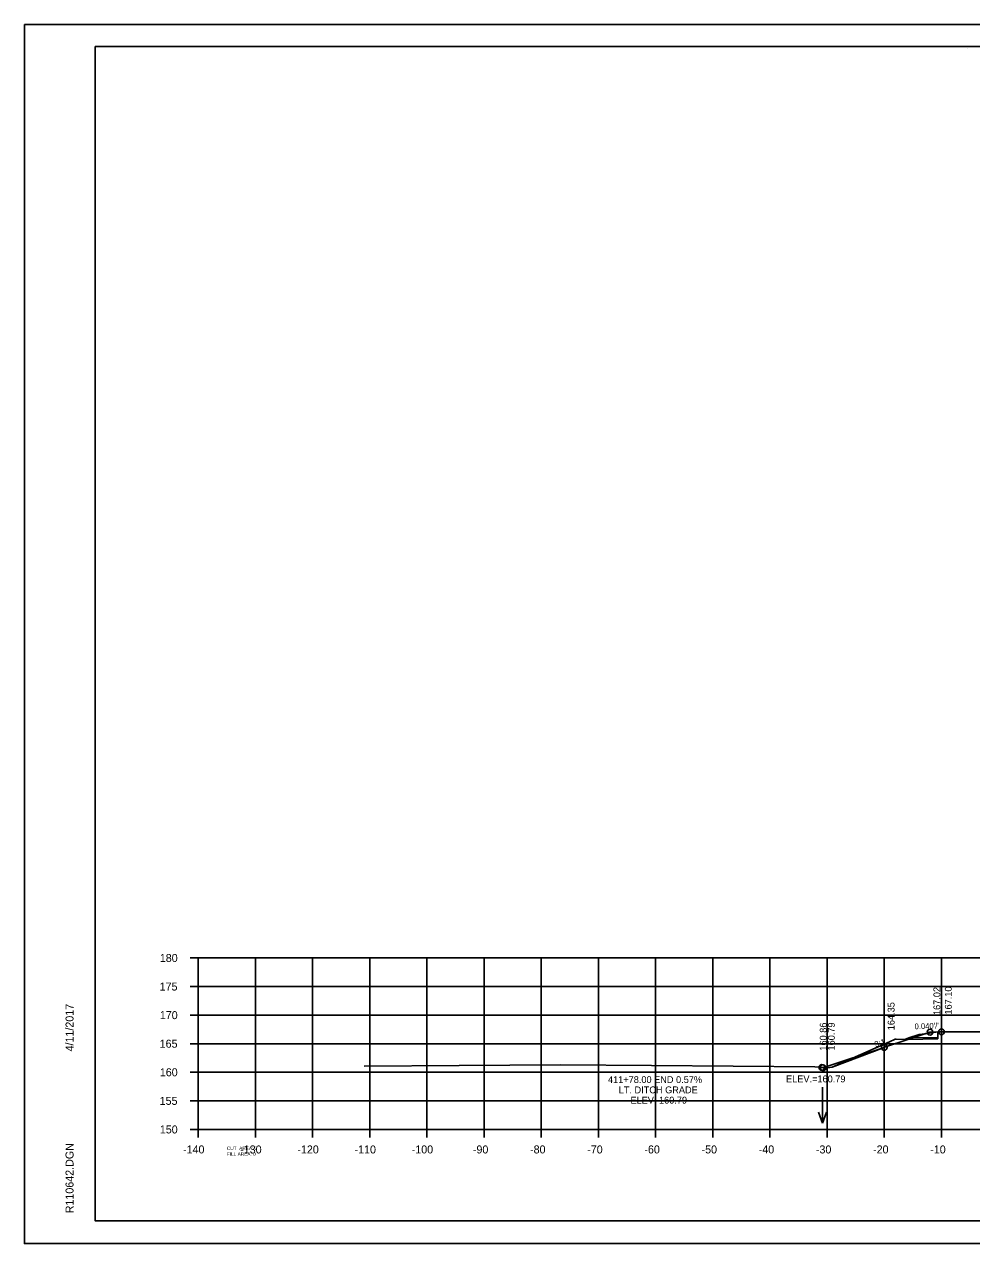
# Model space of a CAD drawing. Extents: x 1368503 to 1373085, y 379840 to 381833.
# Drawn here: x 1368502.7 to 1368668.3, y 381619.4 to 381832.7 of the extents above; entities that cross this region are included whole.
import ezdxf

# ---------------------------------------------------------------- set-up
doc = ezdxf.new("R2010")
doc.units = 0
for name, color, linetype in [('S_BRIDGE', 7, 'Continuous'), ('S_EDGE_PAVEMENT', 7, 'Continuous'), ('S_GRAVEL_ROAD', 7, 'Continuous'), ('S_MISC_BOUNDARY', 7, 'Continuous'), ('S_OBSCURES', 7, 'Continuous'), ('S_PHOTO_CENTERS', 7, 'Continuous'), ('S_PHOTO_NOTES', 7, 'Continuous'), ('S_RDW_PT_SYM', 7, 'Continuous'), ('S_SHOULDER', 7, 'Continuous'), ('S_STREAM_ANNOT', 7, 'Continuous'), ('S_TRAILS', 7, 'Continuous'), ('S_TREE', 7, 'Continuous')]:
    doc.layers.add(name, color=color, linetype=linetype)

msp = doc.modelspace()

# ---------------------------------------------------------------- linework, layer by layer
at = {"layer": 'S_BRIDGE'}
for p, q in [((1368515.06, 381828.85), (1368831.24, 381828.85)), ((1368515.06, 381623.39), (1368515.06, 381828.85)), ((1368667.58, 381828.59), (1368667.58, 381828.59)), ((1368667.58, 381828.59), (1368667.58, 381828.59)), ((1368515.06, 381623.39), (1368515.06, 381623.39)), ((1368831.24, 381623.39), (1368515.06, 381623.39))]:
    msp.add_line(p, q, dxfattribs=at)
at = {"layer": 'S_EDGE_PAVEMENT'}
for p, q in [((1368531.66, 381669.39), (1368533.06, 381669.39)), ((1368533.06, 381639.39), (1368533.06, 381669.39)), ((1368531.66, 381664.39), (1368533.06, 381664.39)), ((1368531.66, 381659.39), (1368533.06, 381659.39)), ((1368531.66, 381654.39), (1368533.06, 381654.39)), ((1368531.66, 381649.39), (1368533.06, 381649.39)), ((1368531.66, 381644.39), (1368533.06, 381644.39)), ((1368531.66, 381639.39), (1368533.06, 381639.39)), ((1368533.06, 381639.39), (1368813.06, 381639.39)), ((1368533.06, 381637.99), (1368533.06, 381639.39)), ((1368543.06, 381637.99), (1368543.06, 381639.39)), ((1368553.06, 381637.99), (1368553.06, 381639.39)), ((1368563.06, 381637.99), (1368563.06, 381639.39)), ((1368573.06, 381637.99), (1368573.06, 381639.39)), ((1368583.06, 381637.99), (1368583.06, 381639.39)), ((1368593.06, 381637.99), (1368593.06, 381639.39)), ((1368603.06, 381637.99), (1368603.06, 381639.39)), ((1368613.06, 381637.99), (1368613.06, 381639.39)), ((1368623.06, 381637.99), (1368623.06, 381639.39)), ((1368633.06, 381637.99), (1368633.06, 381639.39)), ((1368643.06, 381637.99), (1368643.06, 381639.39)), ((1368653.06, 381637.99), (1368653.06, 381639.39)), ((1368663.06, 381637.99), (1368663.06, 381639.39))]:
    msp.add_line(p, q, dxfattribs=at)
at = {"layer": 'S_GRAVEL_ROAD'}
for p, q in [((1368642.25, 381646.77), (1368642.25, 381640.49)), ((1368642.25, 381640.49), (1368641.55, 381642.41)), ((1368642.25, 381640.49), (1368642.95, 381642.41))]:
    msp.add_line(p, q, dxfattribs=at)
at = {"layer": 'S_MISC_BOUNDARY'}
msp.add_lwpolyline([(1368562.08, 381650.45), (1368578.71, 381650.55), (1368596.44, 381650.69), (1368612.33, 381650.58), (1368640.89, 381650.34), (1368643.15, 381650.19), (1368643.95, 381650.26), (1368653.95, 381654.72), (1368654.99, 381655.17), (1368655.16, 381655.17), (1368656.64, 381655.14), (1368657.35, 381655.41), (1368659.19, 381655.99), (1368660.23, 381656.12), (1368662.4, 381656.45), (1368670.18, 381656.48)], dxfattribs=at)
at = {"layer": 'S_OBSCURES'}
for points in [[(1368662.4, 381655.23), (1368657.19, 381655.13)], [(1368662.4, 381655.48), (1368657.99, 381655.39)]]:
    msp.add_lwpolyline(points, dxfattribs=at)
at = {"layer": 'S_PHOTO_CENTERS'}
for p, q in [((1368533.06, 381669.39), (1368813.06, 381669.39)), ((1368533.06, 381639.39), (1368533.06, 381669.39)), ((1368543.06, 381639.39), (1368543.06, 381669.39)), ((1368553.06, 381639.39), (1368553.06, 381669.39)), ((1368563.06, 381639.39), (1368563.06, 381669.39)), ((1368573.06, 381639.39), (1368573.06, 381669.39)), ((1368583.06, 381639.39), (1368583.06, 381669.39)), ((1368593.06, 381639.39), (1368593.06, 381669.39)), ((1368603.06, 381639.39), (1368603.06, 381669.39)), ((1368613.06, 381639.39), (1368613.06, 381669.39)), ((1368623.06, 381639.39), (1368623.06, 381669.39)), ((1368633.06, 381639.39), (1368633.06, 381669.39)), ((1368643.06, 381639.39), (1368643.06, 381669.39)), ((1368653.06, 381639.39), (1368653.06, 381669.39)), ((1368663.06, 381639.39), (1368663.06, 381669.39)), ((1368533.06, 381664.39), (1368813.06, 381664.39)), ((1368533.06, 381659.39), (1368813.06, 381659.39)), ((1368533.06, 381654.39), (1368813.06, 381654.39)), ((1368533.06, 381649.39), (1368813.06, 381649.39)), ((1368533.06, 381644.39), (1368813.06, 381644.39)), ((1368533.06, 381639.39), (1368813.06, 381639.39))]:
    msp.add_line(p, q, dxfattribs=at)
at = {"layer": 'S_PHOTO_NOTES'}
for p, q in [((1368502.66, 381832.75), (1368835.99, 381832.75)), ((1368502.66, 381619.42), (1368835.99, 381619.42))]:
    msp.add_line(p, q, dxfattribs=at)
for points in [[(1368502.65, 381832.75), (1368835.99, 381832.75), (1368835.99, 381619.41), (1368502.65, 381619.41)], [(1368748.98, 381828.85), (1368748.98, 381818.97), (1368784.71, 381818.97), (1368784.71, 381816.05), (1368807.91, 381816.05), (1368807.91, 381791.72), (1368831.24, 381791.72), (1368831.24, 381623.39), (1368515.06, 381623.39), (1368515.06, 381828.85)], [(1368643.95, 381650.26), (1368653.95, 381654.72), (1368653.09, 381653.76), (1368653.06, 381653.75)], [(1368656.64, 381655.14), (1368657.35, 381655.41), (1368657.19, 381655.13)], [(1368660.23, 381656.12), (1368662.4, 381656.45), (1368662.4, 381656.47), (1368661.07, 381656.42), (1368661.06, 381656.41), (1368661.02, 381656.4)], [(1368642.15, 381650.25), (1368642.15, 381650.25), (1368643.15, 381650.19), (1368642.46, 381650.22), (1368642.36, 381650.18), (1368642.16, 381650.25)]]:
    msp.add_lwpolyline(points, close=True, dxfattribs=at)
for centre in [(1368661.06, 381656.41), (1368663.06, 381656.49), (1368653.06, 381653.75), (1368642.15, 381650.25), (1368642.36, 381650.18)]:
    msp.add_circle(centre, 0.5, dxfattribs=at)
at = {"layer": 'S_STREAM_ANNOT'}
msp.add_lwpolyline([(1368642.15, 381650.25), (1368642.16, 381650.25), (1368642.36, 381650.18), (1368642.46, 381650.22), (1368653.06, 381653.75), (1368653.09, 381653.76), (1368657.19, 381655.13), (1368661.02, 381656.4), (1368661.06, 381656.41), (1368661.07, 381656.42), (1368662.4, 381656.47)], dxfattribs=at)
at = {"layer": 'S_TREE'}
msp.add_line((1368662.4, 381655.23), (1368662.4, 381656.47), dxfattribs=at)

# ---------------------------------------------------------------- texts
at = {"layer": 'S_BRIDGE'}
for s, p in [('4/11/2017', (1368511.25, 381653.04)), ('R110642.DGN', (1368511.25, 381624.72))]:
    msp.add_text(s, height=1.4, rotation=90, dxfattribs=at).set_placement(p)
at = {"layer": 'S_GRAVEL_ROAD'}
for s, p in [('411+78.00 END 0.57%', (1368604.73, 381647.51)), ('ELEV.=160.79', (1368635.88, 381647.63)), ('LT. DITCH GRADE', (1368606.61, 381645.71)), ('ELEV. 160.79', (1368608.66, 381643.91))]:
    msp.add_text(s, height=1.2, dxfattribs=at).set_placement(p)
at = {"layer": 'S_RDW_PT_SYM'}
for s, rotation, p in [("0.040'/'", 2.2906, (1368658.38, 381656.91)), ('3:1', 18.434, (1368651.55, 381653.77))]:
    msp.add_text(s, height=1, rotation=rotation, dxfattribs=at).set_placement(p)
at = {"layer": 'S_SHOULDER'}
for s, p in [('167.02', (1368662.86, 381659.41)), ('167.10', (1368664.86, 381659.49)), ('164.35', (1368654.86, 381656.75)), ('160.86', (1368642.98, 381653.18)), ('160.79', (1368644.4, 381653.2))]:
    msp.add_text(s, height=1.2, rotation=90, dxfattribs=at).set_placement(p)
at = {"layer": 'S_TRAILS'}
for s, height, p in [('180', 1.4, (1368526.34, 381668.69)), ('175', 1.4, (1368526.31, 381663.69)), ('170', 1.4, (1368526.34, 381658.69)), ('165', 1.4, (1368526.31, 381653.69)), ('160', 1.4, (1368526.34, 381648.69)), ('155', 1.4, (1368526.31, 381643.69)), ('150', 1.4, (1368526.34, 381638.69)), ('-140', 1.4, (1368530.4, 381635.19)), ('CUT  AREA: 3', 0.6, (1368538.06, 381635.79)), ('FILL AREA: 0', 0.6, (1368538.06, 381634.79)), ('-130', 1.4, (1368540.4, 381635.19)), ('-120', 1.4, (1368550.4, 381635.19)), ('-110', 1.4, (1368560.4, 381635.19)), ('-100', 1.4, (1368570.4, 381635.19)), ('-90', 1.4, (1368581.1, 381635.19)), ('-80', 1.4, (1368591.1, 381635.19)), ('-70', 1.4, (1368601.1, 381635.19)), ('-60', 1.4, (1368611.1, 381635.19)), ('-50', 1.4, (1368621.1, 381635.19)), ('-40', 1.4, (1368631.1, 381635.19)), ('-30', 1.4, (1368641.1, 381635.19)), ('-20', 1.4, (1368651.1, 381635.19)), ('-10', 1.4, (1368661.1, 381635.19))]:
    msp.add_text(s, height=height, dxfattribs=at).set_placement(p)

doc.saveas('drawing.dxf')
